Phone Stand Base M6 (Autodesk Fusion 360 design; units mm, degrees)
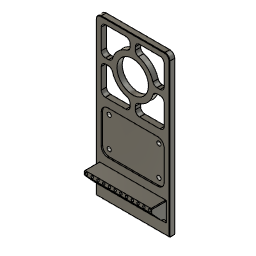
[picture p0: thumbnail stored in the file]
sketch "Sketch1" plane through (0, 0, 0) normal (0, 0, 1) x axis (1, 0, 0)
  line L1 (190.5, 0) -> (0, 0)
  line L2 (190.5, 88.9) -> (190.5, 0)
  line L3 (0, 88.9) -> (190.5, 88.9)
  line L4 (0, 0) -> (0, 88.9)
  point P1 (0, 0)
  point P2 (0, 0)
  point P3 (190.5, 0)
  point P5 (0, 88.9)
  horizontal L1
  vertical L2
  horizontal L3
  vertical L4
  coincident P1 P2
  dimension "d1" distance P2 P3 = 190.5
  dimension "d2" distance P2 P5 = 88.9
extrude "Extrude1" new body sketch "Sketch1" along normal blind 6.35
sketch "Sketch2" plane through (0, 0, 6.35) normal (0, 0, 1) x axis (-1, 0, 0)
  line L1 (0, 0) -> (0, -88.9)
  line L2 (-190.5, 0) -> (0, 0)
  line L3 (-190.5, -88.9) -> (-190.5, 0)
  line L4 (0, -88.9) -> (-190.5, -88.9)
  line L5 (-36.83, -85.09) -> (-19.05, -85.09)
  line L6 (-36.83, -3.81) -> (-36.83, -85.09)
  line L7 (-19.05, -3.81) -> (-36.83, -3.81)
  line L8 (-19.05, -85.09) -> (-19.05, -3.81)
  horizontal L5
  vertical L6
  horizontal L7
  vertical L8
  dimension "d5" distance L1 L8 = 19.05
  dimension "d6" distance L6 L8 = 17.78
  dimension "d7" distance L4 L5 = 3.81
  dimension "d8" distance L2 L7 = 3.81
extrude "Extrude2" add sketch "Sketch2" profile of L5 L6 L7 L8 along normal blind 17.78
fillet "Fillet1" radius 6
chamfer "Chamfer1" distance 12.7 distance 11.43
fillet "Fillet2" radius 6
chamfer "Chamfer2" distance 0.5 distance 0.508
fillet "Fillet4" radius 0.75
sketch "Sketch5" plane through (0, 0, 6.35) normal (0, 0, 1) x axis (-1, 0, 0)
  line L1 (-36.08, -85.09) -> (-13.05, -85.09)
  line L2 (-36.83, -4.56) -> (-36.83, -84.34)
  line L3 (-13.05, -3.81) -> (-36.08, -3.81)
  line L4 (-13.05, -85.09) -> (-13.05, -3.81)
  line L5 (-184.5, -0.5) -> (-0.5, -0.5)
  line L6 (-190, -82.9) -> (-190, -6)
  line L7 (-0.5, -88.4) -> (-184.5, -88.4)
  line L8 (-0.5, -0.5) -> (-0.5, -88.4)
  line L9 (0, -88.9) -> (-184.5, -88.9)
  line L10 (-190.5, -82.9) -> (-190.5, -6)
  line L11 (-184.15, -77.47) -> (-184.15, -52.705)
  line L12 (-154.305, -82.55) -> (-179.07, -82.55)
  line L13 (-184.15, -44.45) -> (-171.45, -44.45)
  line L14 (-190.5, -44.45) -> (-190, -44.45)
  line L15 (-179.07, -47.625) -> (-171.2508, -47.625)
  line L16 (-146.05, -82.55) -> (-146.05, -69.85)
  line L17 (-146.05, -88.9) -> (-146.05, -88.4)
  line L18 (-149.225, -77.47) -> (-149.225, -69.6508)
  line L19 (-149.225, -88.9) -> (-149.225, -88.4)
  arc A1 centre (-36.08, -84.34) radius 0.75 clockwise from (-36.08, -85.09) to (-36.83, -84.34)
  arc A2 centre (-36.08, -4.56) radius 0.75 clockwise from (-36.83, -4.56) to (-36.08, -3.81)
  arc A3 centre (-184.5, -6) radius 5.5 clockwise from (-190, -6) to (-184.5, -0.5)
  arc A4 centre (-184.5, -82.9) radius 5.5 clockwise from (-184.5, -88.4) to (-190, -82.9)
  circle C1 centre (-146.05, -44.45) radius 19.05
  circle C2 centre (-146.05, -44.45) radius 25.4
  arc A5 centre (-179.07, -77.47) radius 5.08 clockwise from (-179.07, -82.55) to (-184.15, -77.47)
  arc A6 centre (-154.305, -77.47) radius 5.08 clockwise from (-149.225, -77.47) to (-154.305, -82.55)
  arc A7 centre (-179.07, -52.705) radius 5.08 clockwise from (-184.15, -52.705) to (-179.07, -47.625)
  point P24 (-149.225, -69.6508)
  point P25 (-146.05, -69.85)
  point P26 (-171.2508, -47.625)
  point P27 (-171.45, -44.45)
  point P28 (-190.5, -44.45)
  point P29 (-184.15, -44.45)
  point P30 (-190, -44.45)
  point P31 (-146.05, -82.55)
  point P32 (-146.05, -88.4)
  point P33 (-149.225, -88.4)
  point P34 (-149.225, -88.9)
  point P35 (-146.05, -88.9)
  point P18 (-146.05, -44.45)
  coincident C2 P24
  coincident C2 P25
  coincident C2 P26
  coincident C2 P27
  coincident L10 P28
  coincident L11 P29
  coincident L6 P30
  collinear L13 L14
  coincident L12 P31
  coincident L7 P32
  collinear L16 L17
  coincident L7 P33
  collinear L18 L19
  coincident L9 P34
  coincident L9 P35
  tangent L12 A5
  tangent L11 A5
  tangent L18 A6
  tangent L12 A6
  tangent L11 A7
  tangent L15 A7
  dimension "d51" distance P18 L9 = 44.45
  dimension "d52" distance P18 L10 = 44.45
  dimension "d53" diameter C1 = 38.1
  dimension "d54" = 6.35
  dimension "d58" radius A5 = 5.08
  dimension "d59" radius A6 = 5.08
  dimension "d60" radius A7 = 5.08
extrude "Extrude5" cut sketch "Sketch5" profile of C1 C2 L19 L15 L11 L12 A5 A6 A7 no distance stored
fillet "Fillet5" radius 5
fillet "Fillet6" radius 5
circular_pattern "C-Pattern1" TotalAngle 360
fillet "Fillet7" radius 5
sketch "Sketch6" plane through (0, 0, 6.35) normal (0, 0, 1) x axis (-1, 0, 0)
  line L1 (-107.95, -77.47) -> (-107.95, -52.705)
  line L2 (-137.795, -82.55) -> (-113.03, -82.55)
  line L3 (-142.875, -73.7302) -> (-142.875, -77.47)
  line L4 (-113.03, -47.625) -> (-116.7698, -47.625)
  line L5 (-113.03, -6.35) -> (-137.795, -6.35)
  line L6 (-107.95, -36.195) -> (-107.95, -11.43)
  line L7 (-116.7698, -41.275) -> (-113.03, -41.275)
  line L8 (-142.875, -11.43) -> (-142.875, -15.1698)
  line L9 (-184.15, -11.43) -> (-184.15, -36.195)
  line L10 (-154.305, -6.35) -> (-179.07, -6.35)
  line L11 (-149.225, -15.1698) -> (-149.225, -11.43)
  line L12 (-179.07, -41.275) -> (-175.3302, -41.275)
  line L13 (-179.07, -82.55) -> (-154.305, -82.55)
  line L14 (-184.15, -52.705) -> (-184.15, -77.47)
  line L15 (-175.3302, -47.625) -> (-179.07, -47.625)
  line L16 (-149.225, -77.47) -> (-149.225, -73.7302)
  line L17 (-36.08, -85.09) -> (-13.05, -85.09)
  line L18 (-36.83, -4.56) -> (-36.83, -84.34)
  line L19 (-13.05, -3.81) -> (-36.08, -3.81)
  line L20 (-13.05, -85.09) -> (-13.05, -3.81)
  line L21 (-184.5, -0.5) -> (-0.5, -0.5)
  line L22 (-190, -82.9) -> (-190, -6)
  line L23 (-0.5, -88.4) -> (-184.5, -88.4)
  line L24 (-0.5, -0.5) -> (-0.5, -88.4)
  line L25 (-46.355, -82.55) -> (-98.425, -82.55)
  line L26 (-46.355, -6.35) -> (-46.355, -82.55)
  line L27 (-98.425, -6.35) -> (-46.355, -6.35)
  line L28 (-98.425, -82.55) -> (-98.425, -6.35)
  line L29 (0, -88.9) -> (-184.5, -88.9)
  arc A1 centre (-113.03, -52.705) radius 5.08 clockwise from (-113.03, -47.625) to (-107.95, -52.705)
  arc A2 centre (-113.03, -77.47) radius 5.08 clockwise from (-107.95, -77.47) to (-113.03, -82.55)
  arc A3 centre (-137.795, -77.47) radius 5.08 clockwise from (-137.795, -82.55) to (-142.875, -77.47)
  arc A4 centre (-137.875, -73.7302) radius 5 clockwise from (-142.875, -73.7302) to (-139.2196, -68.9144)
  arc A5 centre (-146.05, -44.45) radius 25.4 clockwise from (-121.5856, -51.2804) to (-139.2196, -68.9144)
  arc A6 centre (-116.7698, -52.625) radius 5 clockwise from (-121.5856, -51.2804) to (-116.7698, -47.625)
  arc A7 centre (-137.795, -11.43) radius 5.08 clockwise from (-142.875, -11.43) to (-137.795, -6.35)
  arc A8 centre (-113.03, -11.43) radius 5.08 clockwise from (-113.03, -6.35) to (-107.95, -11.43)
  arc A9 centre (-113.03, -36.195) radius 5.08 clockwise from (-107.95, -36.195) to (-113.03, -41.275)
  arc A10 centre (-116.7698, -36.275) radius 5 clockwise from (-116.7698, -41.275) to (-121.5856, -37.6196)
  arc A11 centre (-146.05, -44.45) radius 25.4 clockwise from (-139.2196, -19.9856) to (-121.5856, -37.6196)
  arc A12 centre (-137.875, -15.1698) radius 5 clockwise from (-139.2196, -19.9856) to (-142.875, -15.1698)
  arc A13 centre (-179.07, -36.195) radius 5.08 clockwise from (-179.07, -41.275) to (-184.15, -36.195)
  arc A14 centre (-179.07, -11.43) radius 5.08 clockwise from (-184.15, -11.43) to (-179.07, -6.35)
  arc A15 centre (-154.305, -11.43) radius 5.08 clockwise from (-154.305, -6.35) to (-149.225, -11.43)
  arc A16 centre (-154.225, -15.1698) radius 5 clockwise from (-149.225, -15.1698) to (-152.8804, -19.9856)
  arc A17 centre (-146.05, -44.45) radius 25.4 clockwise from (-170.5144, -37.6196) to (-152.8804, -19.9856)
  arc A18 centre (-175.3302, -36.275) radius 5 clockwise from (-170.5144, -37.6196) to (-175.3302, -41.275)
  arc A19 centre (-154.305, -77.47) radius 5.08 clockwise from (-149.225, -77.47) to (-154.305, -82.55)
  arc A20 centre (-179.07, -77.47) radius 5.08 clockwise from (-179.07, -82.55) to (-184.15, -77.47)
  arc A21 centre (-179.07, -52.705) radius 5.08 clockwise from (-184.15, -52.705) to (-179.07, -47.625)
  arc A22 centre (-175.3302, -52.625) radius 5 clockwise from (-175.3302, -47.625) to (-170.5144, -51.2804)
  arc A23 centre (-146.05, -44.45) radius 25.4 clockwise from (-152.8804, -68.9144) to (-170.5144, -51.2804)
  arc A24 centre (-154.225, -73.7302) radius 5 clockwise from (-152.8804, -68.9144) to (-149.225, -73.7302)
  circle C1 centre (-146.05, -44.45) radius 19.05
  arc A25 centre (-36.08, -84.34) radius 0.75 clockwise from (-36.08, -85.09) to (-36.83, -84.34)
  arc A26 centre (-36.08, -4.56) radius 0.75 clockwise from (-36.83, -4.56) to (-36.08, -3.81)
  arc A27 centre (-184.5, -6) radius 5.5 clockwise from (-190, -6) to (-184.5, -0.5)
  arc A28 centre (-184.5, -82.9) radius 5.5 clockwise from (-184.5, -88.4) to (-190, -82.9)
  horizontal L25
  vertical L26
  horizontal L27
  vertical L28
  dimension "d70" distance L25 L29 = 6.35
  dimension "d71" distance L25 L27 = 76.2
  dimension "d72" distance L6 L28 = 9.525
  dimension "d73" distance L18 L26 = 9.525
extrude "Extrude6" cut sketch "Sketch6" profile of L25 L26 L27 L28 against normal blind 1.6
fillet "Fillet8" radius 8
hole "Hole2" HoleDiameter 5.035 TipAngle 118
hole "Hole3" HoleDiameter 5.035 TipAngle 118
hole "Hole4" HoleDiameter 5.035 TipAngle 118
hole "Hole5" HoleDepth 30.48 HoleDiameter 5.035 TipAngle 118
hole "Hole6" HoleDepth 24.13 HoleDiameter 3 TipAngle 118 RefDim1 2.54 RefDim2 6.35
rectangular_pattern "R-Pattern2" countU 12 uSpaceDistance 76.2 vSpaceDistance 0
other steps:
thread "Thread2"
thread "Thread3"
thread "Thread4"
thread "Thread5"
